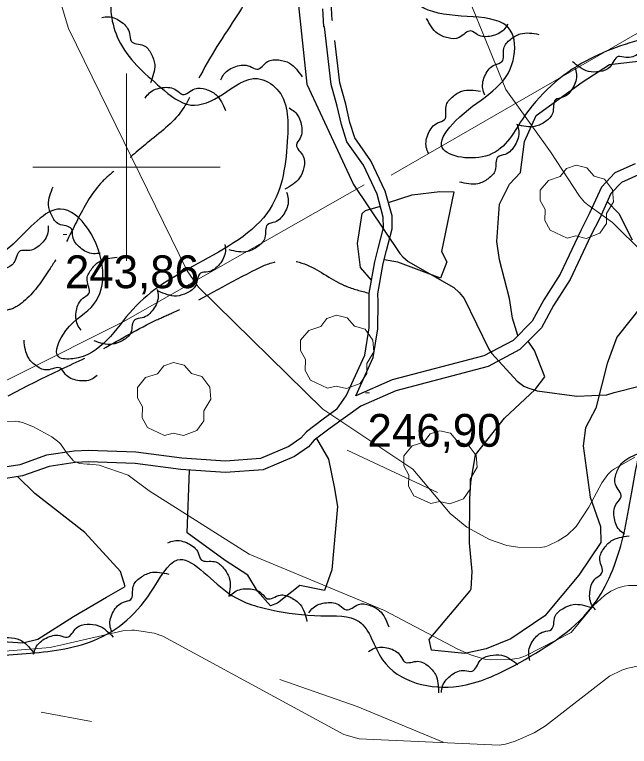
# Model space of a CAD drawing. Extents: x 480269 to 484877, y 4383588 to 4386804.
# Drawn here: x 483470.1 to 483634.3, y 4385345.4 to 4385540.7 of the extents above; entities that cross this region are included whole.
import ezdxf

# ---------------------------------------------------------------- set-up
doc = ezdxf.new("R2010")
doc.units = 0
doc.header["$LTSCALE"] = 3.8
doc.linetypes.add('LONG_DASHED', pattern=[7.5, 6, -1.5])
doc.linetypes.add('MEDIUM_DASHED', pattern=[4.5, 3, -1.5])
for name, color, linetype, lineweight in [('1', 7, 'Continuous', 13), ('25', 7, 'LONG_DASHED', 25), ('27', 7, 'Continuous', 25), ('29', 7, 'Continuous', 13), ('38', 7, 'Continuous', 25), ('51', 7, 'Continuous', 13), ('7', 7, 'Continuous', 13), ('8', 7, 'Continuous', 25), ('9', 7, 'Continuous', 13)]:
    doc.layers.add(name, color=color, linetype=linetype, lineweight=lineweight)

msp = doc.modelspace()

# ---------------------------------------------------------------- linework, layer by layer
at = {"layer": '1'}
for p, q in [((483500, 4385525), (483500, 4385475)), ((483475, 4385500), (483525, 4385500))]:
    msp.add_line(p, q, dxfattribs=at)
at = {"layer": '25'}
for points in [[(483604.54, 4385455.06), (483603.13, 4385459.72), (483602.33, 4385464.95), (483599.66, 4385475.32), (483598.97, 4385480.21), (483599.64, 4385490.14), (483602.36, 4385495.49), (483605.27, 4385498.55), (483606.36, 4385506.84), (483609.46, 4385513.76), (483621.7, 4385522.66), (483629.01, 4385527.38), (483640.73, 4385528.77), (483647.46, 4385528.09), (483656.5, 4385525.57), (483656.93, 4385519.13), (483653.39, 4385515.14), (483647.44, 4385510.87), (483651.9, 4385507.54), (483655.22, 4385504.23)], [(483569.98, 4385490.59), (483576.34, 4385492.58), (483583.7, 4385493.53), (483587.45, 4385493.45), (483584.2, 4385477.46), (483585.56, 4385474.7), (483583.9, 4385470.39), (483572.48, 4385474.63), (483568.86, 4385475.26)], [(483565.46, 4385469.83), (483562.51, 4385473.22), (483561.74, 4385479.61), (483562.97, 4385487.67), (483563.84, 4385488.41), (483567.84, 4385489.6)], [(483628.43, 4385490.8), (483631.55, 4385487.62), (483635.1, 4385480.65)], [(483637.54, 4385462.92), (483630.95, 4385454.65), (483628.38, 4385447.63), (483625.35, 4385435.71), (483622.58, 4385430.41), (483621.96, 4385425.67), (483623.88, 4385411.98), (483626.63, 4385404.12), (483626.74, 4385399.8), (483620.88, 4385391.11), (483611.78, 4385380.29), (483602.69, 4385374.1), (483596.05, 4385371.45), (483590.43, 4385370.22), (483581.47, 4385371.08), (483580.84, 4385373.94), (483591.84, 4385386.97), (483592.05, 4385387.43), (483592.38, 4385392.09), (483591.62, 4385399.76), (483591.76, 4385411.51), (483591.97, 4385415.95), (483593.27, 4385423.22), (483601, 4385432.98), (483609.16, 4385440.64), (483611.73, 4385444.09), (483609, 4385451.06), (483607.32, 4385453.54)], [(483550.76, 4385427.56), (483554, 4385422.06), (483555.52, 4385414.69), (483556.41, 4385409.48), (483554.84, 4385392.51), (483552.91, 4385387.01), (483546.35, 4385388.34), (483540.37, 4385383.68), (483538.47, 4385382.93), (483535.04, 4385386.86), (483532.44, 4385391.15), (483526.35, 4385395.05), (483516.2, 4385402.4), (483516.86, 4385419.18)], [(483409.23, 4385391.99), (483412.22, 4385387.81), (483418.41, 4385380.86), (483426.24, 4385372.32), (483432.23, 4385365.76), (483435.41, 4385363.94), (483440.59, 4385368.76), (483443.75, 4385372.94), (483450.48, 4385375.88), (483462.54, 4385373.64), (483472.32, 4385373.1), (483476.31, 4385374.03), (483485.84, 4385380.07), (483494.71, 4385385.22), (483499.63, 4385388.12), (483498.39, 4385392.12), (483488.93, 4385402.47), (483475.52, 4385412.88), (483470.95, 4385417.41)]]:
    msp.add_lwpolyline(points, dxfattribs=at)
at = {"layer": '27'}
for points in [[(483603.65, 4385366.99), (483624.2, 4385382.47), (483632.03, 4385398.91), (483636.72, 4385422.41), (483645.34, 4385439.65), (483660.21, 4385444.35), (483671.96, 4385455.31), (483662.56, 4385467.06), (483659.43, 4385476.46), (483674.31, 4385492.91), (483694.66, 4385499.96), (483704.06, 4385490.56), (483711.11, 4385468.63), (483722.85, 4385451.4), (483736.16, 4385456.1), (483742.42, 4385467.85), (483748.69, 4385484.3), (483759.65, 4385490.56), (483776.88, 4385484.3), (483802.71, 4385469.41), (483826.99, 4385463.15), (483860.65, 4385463.15), (483873.96, 4385476.46), (483902.15, 4385486.65), (483911.55, 4385506.23), (483932.69, 4385513.28), (483942.86, 4385514.85), (483932.69, 4385531.3), (483915.46, 4385547.75), (483903.72, 4385547.75), (483886.49, 4385539.13), (483871.61, 4385529.73), (483863.78, 4385533.65), (483865.35, 4385544.61), (483871.61, 4385560.28), (483873.96, 4385572.03), (483874.75, 4385588.48), (483884.93, 4385596.31), (483910.76, 4385592.4), (483924.07, 4385597.1), (483936.6, 4385618.25), (483939.73, 4385664.46), (483945.7, 4385679.85)], [(483546.8, 4385573.01), (483530.82, 4385569.72), (483504.5, 4385557.5), (483496.51, 4385547.62), (483497.92, 4385533.98), (483509.2, 4385521.29), (483517.19, 4385516.59), (483525.65, 4385519.41), (483535.05, 4385523.64), (483540.22, 4385520.82), (483543.04, 4385508.12), (483538.34, 4385488.84), (483519.07, 4385474.27), (483501.68, 4385462.04), (483485.7, 4385448.88), (483481.94, 4385449.35), (483483.82, 4385456.4), (483491.34, 4385463.45), (483493.69, 4385472.39), (483482.41, 4385488.84), (483469.72, 4385479.44), (483457.5, 4385473.8), (483447.16, 4385476.15), (483435.41, 4385469.57), (483432.12, 4385452.64), (483431.65, 4385426.31), (483427.89, 4385415.96), (483416.61, 4385410.32), (483407.68, 4385404.21), (483394.53, 4385402.8), (483381.37, 4385399.03), (483373.85, 4385390.57), (483366.33, 4385379.29), (483360.69, 4385372.7), (483348.47, 4385369.41), (483324.97, 4385367.06), (483298.65, 4385356.72), (483277.03, 4385345.43), (483258.23, 4385329.91), (483253.06, 4385332.26), (483259.17, 4385339.32), (483268.1, 4385347.78), (483265.28, 4385357.19), (483251.65, 4385366.59), (483243.66, 4385376.46), (483231.44, 4385369.41), (483229.09, 4385383.05), (483230.97, 4385390.1)], [(483677.76, 4385562.31), (483673.47, 4385559.38), (483664.07, 4385546.21), (483641.98, 4385535.4), (483622.71, 4385528.34), (483605.79, 4385512.83), (483595.92, 4385502.95), (483584.17, 4385505.77), (483587.93, 4385512.36), (483602.97, 4385527.4), (483602.97, 4385535.87), (483581.82, 4385541.51), (483567.25, 4385554.67), (483546.8, 4385573.01)], [(483493.46, 4385539.96), (483495.23, 4385540.15), (483498.73, 4385538.7), (483500.85, 4385535.67), (483501.26, 4385533.66), (483504.61, 4385532.47), (483506.63, 4385530.26), (483507.55, 4385527.38), (483506.43, 4385522.55)], [(483601.83, 4385538.16), (483600.83, 4385536.7), (483597.44, 4385534.99), (483593.77, 4385535.36), (483591.97, 4385536.36), (483588.88, 4385534.6), (483585.9, 4385534.51), (483583.11, 4385535.68), (483580.19, 4385539.69)], [(483595.71, 4385519.26), (483595.17, 4385520.95), (483595.89, 4385524.67), (483598.43, 4385527.35), (483600.31, 4385528.16), (483600.81, 4385531.68), (483602.57, 4385534.1), (483605.2, 4385535.58), (483610.16, 4385535.45)], [(483639.76, 4385534.93), (483639.39, 4385533.2), (483636.9, 4385530.33), (483633.37, 4385529.28), (483631.33, 4385529.52), (483629.13, 4385526.72), (483626.41, 4385525.5), (483623.39, 4385525.54), (483619.16, 4385528.13)], [(483525.22, 4385523.27), (483526.06, 4385524.83), (483529.25, 4385526.89), (483532.94, 4385526.92), (483534.83, 4385526.12), (483537.71, 4385528.2), (483540.67, 4385528.62), (483543.57, 4385527.75), (483546.91, 4385524.08)], [(483619.79, 4385526.56), (483620.22, 4385524.84), (483619.25, 4385521.17), (483616.54, 4385518.66), (483614.6, 4385517.98), (483613.87, 4385514.5), (483611.96, 4385512.21), (483609.23, 4385510.91), (483604.29, 4385511.37)], [(483505.05, 4385518.46), (483506.17, 4385519.83), (483509.68, 4385521.25), (483513.32, 4385520.59), (483515.02, 4385519.44), (483518.25, 4385520.94), (483521.23, 4385520.79), (483523.91, 4385519.38), (483526.49, 4385515.15)], [(483580.69, 4385503.65), (483580.09, 4385505.32), (483580.68, 4385509.06), (483583.12, 4385511.83), (483584.98, 4385512.71), (483585.36, 4385516.24), (483587.02, 4385518.72), (483589.61, 4385520.29), (483594.57, 4385520.33)], [(483543.43, 4385515.8), (483544.92, 4385514.82), (483546.69, 4385511.47), (483546.39, 4385507.79), (483545.42, 4385505.97), (483547.24, 4385502.92), (483547.39, 4385499.93), (483546.26, 4385497.13), (483542.31, 4385494.13)], [(483604.33, 4385511.34), (483604.77, 4385509.62), (483603.83, 4385505.94), (483601.14, 4385503.41), (483599.21, 4385502.71), (483598.51, 4385499.23), (483596.62, 4385496.92), (483593.9, 4385495.59), (483588.96, 4385496.02)], [(483152.78, 4385510.55), (483142.48, 4385493.89), (483124.47, 4385470.39), (483116.64, 4385454.72), (483116.64, 4385442.97), (483122.9, 4385434.36), (483136.21, 4385436.71), (483163.62, 4385469.61), (483173.8, 4385481.36), (483179.28, 4385475.09), (483185.54, 4385443.76), (483202.77, 4385387.36), (483200.42, 4385363.07), (483202.77, 4385344.27), (483193.37, 4385323.91), (483203.55, 4385309.02), (483219.21, 4385299.62), (483231.74, 4385296.49), (483252.09, 4385301.97), (483283.41, 4385323.12), (483318.65, 4385327.04), (483364.06, 4385322.34), (483395.38, 4385316.86), (483400.86, 4385327.82), (483389.11, 4385345.84), (483388.33, 4385359.16), (483402.42, 4385367.77), (483422, 4385368.56), (483431.39, 4385363.86), (483453.32, 4385367.77), (483472.11, 4385370.12), (483490.12, 4385373.26), (483506.56, 4385386.57), (483513.61, 4385395.19), (483526.92, 4385386.57), (483538.66, 4385381.87), (483551.97, 4385380.31), (483562.15, 4385378.74), (483568.41, 4385368.56), (483588.77, 4385361.51), (483603.65, 4385366.99)], [(483492.95, 4385477.04), (483491.18, 4385476.9), (483487.72, 4385478.44), (483485.68, 4385481.52), (483485.32, 4385483.55), (483482, 4385484.83), (483480.05, 4385487.09), (483479.2, 4385489.99), (483480.46, 4385494.79)], [(483542.77, 4385493.3), (483543.22, 4385491.58), (483542.3, 4385487.9), (483539.62, 4385485.36), (483537.69, 4385484.66), (483537, 4385481.17), (483535.12, 4385478.85), (483532.41, 4385477.51), (483527.46, 4385477.92)], [(483479.14, 4385484.34), (483479.05, 4385482.56), (483477.05, 4385479.34), (483473.73, 4385477.74), (483471.67, 4385477.65), (483469.96, 4385474.54), (483467.46, 4385472.9), (483464.47, 4385472.45), (483459.88, 4385474.34)], [(483526.3, 4385479.36), (483526.45, 4385477.59), (483524.9, 4385474.12), (483521.81, 4385472.09), (483519.79, 4385471.73), (483518.5, 4385468.42), (483516.25, 4385466.47), (483513.34, 4385465.62), (483508.55, 4385466.88)], [(483487.93, 4385456.51), (483486.95, 4385457.99), (483486.65, 4385461.77), (483488.37, 4385465.03), (483489.98, 4385466.32), (483489.51, 4385469.85), (483490.55, 4385472.64), (483492.69, 4385474.78), (483497.5, 4385475.98)], [(483508.2, 4385467.34), (483508.47, 4385465.58), (483507.16, 4385462.02), (483504.23, 4385459.78), (483502.23, 4385459.28), (483501.18, 4385455.89), (483499.06, 4385453.78), (483496.22, 4385452.74), (483491.35, 4385453.66)], [(483492.21, 4385444.41), (483490.74, 4385443.42), (483486.96, 4385443.09), (483483.68, 4385444.78), (483482.38, 4385446.37), (483478.86, 4385445.88), (483476.05, 4385446.9), (483473.9, 4385449.02), (483472.66, 4385453.82)], [(483633.02, 4385402.07), (483631.66, 4385403.2), (483630.26, 4385406.73), (483630.97, 4385410.35), (483632.12, 4385412.05), (483630.65, 4385415.29), (483630.83, 4385418.27), (483632.26, 4385420.93), (483636.51, 4385423.48)], [(483511.06, 4385399.75), (483512.74, 4385400.3), (483516.47, 4385399.61), (483519.17, 4385397.1), (483520, 4385395.22), (483523.52, 4385394.74), (483525.95, 4385393.01), (483527.46, 4385390.39), (483527.36, 4385385.43)], [(483625.27, 4385381.83), (483624.25, 4385383.28), (483623.83, 4385387.05), (483625.46, 4385390.37), (483627.02, 4385391.7), (483626.45, 4385395.21), (483627.4, 4385398.04), (483629.48, 4385400.24), (483634.25, 4385401.58)], [(483496.07, 4385375.98), (483495.62, 4385377.7), (483496.53, 4385381.38), (483499.21, 4385383.93), (483501.14, 4385384.63), (483501.82, 4385388.12), (483503.7, 4385390.44), (483506.41, 4385391.79), (483511.35, 4385391.39)], [(483527.61, 4385385.5), (483528.94, 4385386.67), (483532.65, 4385387.5), (483536.12, 4385386.24), (483537.61, 4385384.84), (483541.04, 4385385.78), (483543.96, 4385385.14), (483546.37, 4385383.32), (483548.22, 4385378.72)], [(483548.71, 4385381.06), (483549.86, 4385382.41), (483553.4, 4385383.77), (483557.02, 4385383.04), (483558.71, 4385381.86), (483561.96, 4385383.3), (483564.94, 4385383.09), (483567.59, 4385381.64), (483570.1, 4385377.36)], [(483607.75, 4385368.37), (483607.44, 4385370.12), (483608.65, 4385373.71), (483611.52, 4385376.03), (483613.5, 4385376.58), (483614.47, 4385380), (483616.53, 4385382.16), (483619.34, 4385383.28), (483624.23, 4385382.48)], [(483475.23, 4385370.06), (483475.79, 4385371.75), (483478.57, 4385374.33), (483482.2, 4385374.99), (483484.2, 4385374.53), (483486.68, 4385377.08), (483489.52, 4385378), (483492.52, 4385377.64), (483496.45, 4385374.61)], [(483453.62, 4385367.8), (483454.32, 4385369.43), (483457.32, 4385371.76), (483460.99, 4385372.11), (483462.95, 4385371.48), (483465.64, 4385373.8), (483468.55, 4385374.47), (483471.51, 4385373.85), (483475.15, 4385370.49)], [(483564.69, 4385370.76), (483566.24, 4385371.62), (483570.04, 4385371.63), (483573.16, 4385369.65), (483574.31, 4385367.96), (483577.87, 4385368.14), (483580.57, 4385366.89), (483582.54, 4385364.59), (483583.36, 4385359.7)], [(483584.14, 4385359.81), (483584.46, 4385361.55), (483586.85, 4385364.5), (483590.35, 4385365.67), (483592.39, 4385365.5), (483594.49, 4385368.37), (483597.17, 4385369.68), (483600.2, 4385369.75), (483604.51, 4385367.3)]]:
    msp.add_spline(points, degree=3, dxfattribs=at)
at = {"layer": '29'}
for points in [[(483617.72, 4385481.09), (483613.18, 4385483.21), (483611.77, 4385485.75), (483611.87, 4385488.73), (483610.5, 4385491.14), (483610.54, 4385493.89), (483612.7, 4385496.49), (483615.89, 4385497.49), (483617.54, 4385499.68), (483620.11, 4385500.51), (483622.97, 4385499.86), (483624.92, 4385497.59), (483627.73, 4385496.77), (483629.86, 4385493.92), (483630.1, 4385490.79), (483628.22, 4385487.64), (483628.22, 4385484.96), (483626.4, 4385482.35), (483622.78, 4385481.01), (483620.01, 4385481.64)], [(483553.72, 4385441.05), (483549.18, 4385443.17), (483547.77, 4385445.71), (483547.87, 4385448.69), (483546.5, 4385451.1), (483546.54, 4385453.85), (483548.7, 4385456.45), (483551.89, 4385457.45), (483553.54, 4385459.64), (483556.11, 4385460.47), (483558.97, 4385459.82), (483560.92, 4385457.55), (483563.73, 4385456.73), (483565.86, 4385453.88), (483566.1, 4385450.75), (483564.22, 4385447.6), (483564.22, 4385444.92), (483562.4, 4385442.31), (483558.78, 4385440.97), (483556.01, 4385441.6)], [(483510.16, 4385428.43), (483505.62, 4385430.55), (483504.21, 4385433.09), (483504.31, 4385436.07), (483502.94, 4385438.48), (483502.98, 4385441.23), (483505.14, 4385443.83), (483508.33, 4385444.83), (483509.98, 4385447.02), (483512.55, 4385447.85), (483515.41, 4385447.2), (483517.36, 4385444.93), (483520.17, 4385444.11), (483522.3, 4385441.26), (483522.54, 4385438.13), (483520.66, 4385434.98), (483520.66, 4385432.3), (483518.84, 4385429.69), (483515.22, 4385428.35), (483512.45, 4385428.98)], [(483581.31, 4385410.21), (483576.77, 4385412.33), (483575.36, 4385414.87), (483575.46, 4385417.85), (483574.09, 4385420.26), (483574.13, 4385423.01), (483576.29, 4385425.61), (483579.48, 4385426.61), (483581.13, 4385428.8), (483583.7, 4385429.63), (483586.56, 4385428.98), (483588.51, 4385426.71), (483591.32, 4385425.89), (483593.45, 4385423.04), (483593.69, 4385419.91), (483591.81, 4385416.76), (483591.81, 4385414.08), (483589.99, 4385411.47), (483586.37, 4385410.13), (483583.6, 4385410.76)]]:
    msp.add_lwpolyline(points, close=True, dxfattribs=at)
at = {"layer": '38', "linetype": 'MEDIUM_DASHED'}
msp.add_lwpolyline([(483561.28, 4385439.02), (483565.89, 4385449.17), (483567.14, 4385456.9), (483567.2, 4385464.1), (483567.16, 4385466.2), (483568.62, 4385474.3), (483569.47, 4385477.73), (483570.95, 4385483.54), (483570.94, 4385486.99), (483569.15, 4385493.62), (483565.29, 4385501.69), (483560.98, 4385507.84), (483559.66, 4385511.97), (483558.57, 4385516.81), (483557, 4385522.51), (483555.08, 4385539.19), (483554.99, 4385539.22), (483554.78, 4385542.44), (483554.04, 4385551.25), (483553.79, 4385553.9), (483552.16, 4385563.48), (483550.49, 4385569.01), (483550.22, 4385569.85), (483549.87, 4385576.35)], dxfattribs=at)
at = {"layer": '38'}
for points in [[(483556.23, 4385435.44), (483558.73, 4385438.98), (483563.65, 4385449.84), (483564.82, 4385457.09), (483564.88, 4385464.09), (483564.84, 4385466.39), (483566.35, 4385474.78), (483567.22, 4385478.29), (483568.63, 4385483.82), (483568.62, 4385486.68), (483566.96, 4385492.81), (483563.29, 4385500.52), (483558.87, 4385506.8), (483557.42, 4385511.37), (483556.32, 4385516.25), (483554.71, 4385522.07), (483552.94, 4385537.49), (483552.77, 4385537.55), (483552.47, 4385542.27)], [(483635.86, 4385500.86), (483630.44, 4385498.45), (483626.86, 4385494.68), (483623.67, 4385487.74), (483621.34, 4385483.09), (483615.86, 4385471.47), (483611.48, 4385464.63), (483608.41, 4385458.93), (483603.26, 4385453.78), (483595.49, 4385449.63), (483570.98, 4385443.23), (483561.28, 4385439.02)], [(483636.74, 4385497.93), (483632.23, 4385495.92), (483629.41, 4385492.95), (483626.41, 4385486.42), (483624.07, 4385481.76), (483618.52, 4385470), (483614.1, 4385463.09), (483610.87, 4385457.1), (483605.09, 4385451.31), (483596.6, 4385446.78), (483571.98, 4385440.35), (483562.58, 4385436.26), (483554.38, 4385430.36), (483550.19, 4385427.11), (483548.62, 4385425.35), (483544.89, 4385422.77), (483536.57, 4385419.22), (483526.47, 4385418.53), (483514.53, 4385419.34), (483502.3, 4385420.9), (483489.91, 4385421.33), (483486.34, 4385421.2), (483479.37, 4385420.15), (483472.26, 4385417.61), (483467.79, 4385416.91)], [(483556.23, 4385435.44), (483552.56, 4385432.79), (483548.11, 4385429.34), (483546.59, 4385427.64), (483543.41, 4385425.44), (483535.85, 4385422.22), (483526.47, 4385421.57), (483514.83, 4385422.36), (483502.55, 4385423.93), (483489.91, 4385424.37), (483486.06, 4385424.23), (483478.63, 4385423.11), (483471.51, 4385420.57), (483467.56, 4385419.95)]]:
    msp.add_lwpolyline(points, dxfattribs=at)
at = {"layer": '38', "linetype": 'LONG_DASHED'}
for points in [[(483222.84, 4385328.78), (483233.49, 4385331.65), (483248.44, 4385336.61), (483252.54, 4385340.94), (483258.88, 4385354.18), (483261.76, 4385364.09), (483264.07, 4385370.4), (483271.55, 4385381.16), (483280.42, 4385394.23), (483287.47, 4385408.23), (483295.91, 4385425.29), (483304.52, 4385439.96), (483308.91, 4385446.59), (483318.63, 4385460.51), (483325.16, 4385473.38), (483329.03, 4385484.99), (483336.9, 4385500.43), (483342.08, 4385509.3), (483351.29, 4385526.25), (483356.88, 4385535.07), (483367.82, 4385552.46), (483372.61, 4385560.56), (483384.55, 4385574.31), (483394.22, 4385589.19), (483401.11, 4385600.15), (483408.96, 4385613.82), (483416.11, 4385628.46), (483421.62, 4385644.25), (483425.26, 4385652.82), (483437.44, 4385668.5), (483447.61, 4385682.66), (483455.49, 4385695.61), (483457.94, 4385709.1), (483457.8, 4385712.22), (483460.32, 4385716.64), (483471.95, 4385728.32), (483483.41, 4385737.85), (483491.91, 4385744.84), (483502.88, 4385754.26), (483511.53, 4385762), (483517.86, 4385770.14), (483520.82, 4385773.68), (483521.2, 4385789.84), (483522.3, 4385808.2), (483521.83, 4385825.17), (483522.61, 4385837.11), (483524.33, 4385844.04), (483529.61, 4385862.88), (483530.12, 4385879.57), (483529.5, 4385895.4), (483531.44, 4385911.89), (483533.11, 4385922.24), (483534.94, 4385934.41), (483535.75, 4385947.11), (483535.49, 4385954.95), (483538.08, 4385971.48), (483542.8, 4385983), (483551.34, 4385997.49), (483555.36, 4386004.16), (483555.47, 4386004.25)], [(483549.18, 4385565.2), (483543.95, 4385560.32), (483538.38, 4385553.83), (483529.64, 4385540.66), (483519.21, 4385523.41), (483514.75, 4385515.06), (483505.58, 4385506.46), (483497.79, 4385499.89), (483493.59, 4385496.17), (483487.25, 4385486.55), (483482.3, 4385477.14), (483479.01, 4385472.04), (483472.56, 4385464.14), (483468.73, 4385461.99), (483458.51, 4385464.43), (483444.6, 4385463.08), (483435.34, 4385459.51), (483429.43, 4385458.44), (483416.58, 4385458.99), (483403.28, 4385460.76), (483384.88, 4385459.21), (483372.63, 4385454.93), (483365.84, 4385453.56), (483350.1, 4385452.09), (483330.85, 4385457.31), (483319.64, 4385462.11)], [(483448.32, 4385419.72), (483455.27, 4385430.15), (483467.44, 4385438.46), (483480.95, 4385445.3), (483493.72, 4385451.49), (483508.08, 4385459.24), (483512.5, 4385461.23), (483533.63, 4385472.27), (483539.58, 4385474.69), (483545.47, 4385474.8), (483555.97, 4385469.57), (483558.51, 4385468.33), (483564.84, 4385466.39)], [(483795.58, 4385215.69), (483787.52, 4385217.14), (483774.93, 4385219.27), (483756.17, 4385220.84), (483744.1, 4385220.75), (483730.15, 4385220.39), (483717.93, 4385220.89), (483709.9, 4385222.06), (483700.53, 4385223.65), (483694.72, 4385225.88), (483683.27, 4385233.26), (483677.29, 4385236.66), (483662.64, 4385243.79), (483651.72, 4385247.83), (483644.93, 4385250.29), (483635.65, 4385253.31), (483617.57, 4385261.54), (483615.06, 4385263.27), (483612.3, 4385264.61), (483604.76, 4385269), (483594.29, 4385275.78), (483584.82, 4385280.7), (483566.04, 4385290.4), (483555.24, 4385295.34), (483546.21, 4385301.34), (483538.99, 4385305.85), (483528.92, 4385311.04), (483523.21, 4385313.51), (483510.9, 4385315.71), (483494.14, 4385318.51), (483477.95, 4385321.32), (483473.72, 4385322.41), (483455.31, 4385325.65), (483446.94, 4385324.54), (483441.74, 4385325.11), (483434.23, 4385329.08), (483424.38, 4385339.16), (483421.39, 4385345.15), (483417.87, 4385349.13), (483413.47, 4385355.82), (483410.01, 4385363.32), (483406.1, 4385367.21), (483401.43, 4385368.01), (483387.69, 4385374.61)]]:
    msp.add_spline(points, degree=3, dxfattribs=at)
at = {"layer": '51'}
for p, q in [((483570.67, 4385497.84), (483639.54, 4385537.55)), ((483583.09, 4385413.19), (483558.97, 4385424.44)), ((483490.67, 4385352.03), (483477.2, 4385354.57))]:
    msp.add_line(p, q, dxfattribs=at)
for points in [[(483563.54, 4385495.27), (483499.12, 4385458.71), (483444.19, 4385431.26), (483381.87, 4385397.66), (483307.68, 4385358.43), (483243.32, 4385321.98), (483241.23, 4385329.71)], [(483584.63, 4385346.55), (483561.65, 4385356.06), (483541, 4385363.25)]]:
    msp.add_lwpolyline(points, dxfattribs=at)
at = {"layer": '7'}
for p, q in [((483483.09, 4385482.08), (483484.09, 4385482.08)), ((483563.9, 4385439.76), (483564.9, 4385439.76))]:
    msp.add_line(p, q, dxfattribs=at)
at = {"layer": '8'}
for points in [[(483753.34, 4386095.07), (483741.77, 4386077.52), (483729.02, 4386044.1), (483719.89, 4385998.13), (483700.85, 4385936.57), (483673.49, 4385898.65), (483634.96, 4385827.01), (483619.32, 4385779.29), (483617.06, 4385750.43), (483607.42, 4385703.77), (483588.4, 4385668.48), (483553.23, 4385618.74), (483549.49, 4385606.42), (483542.9, 4385571.76), (483548.23, 4385522.15)], [(483548.23, 4385522.15), (483560.67, 4385495.42), (483573.04, 4385476.99), (483573.83, 4385476.1), (483575.24, 4385474.85), (483587.46, 4385467.85), (483588.9, 4385466.55), (483590.17, 4385464.98), (483596.81, 4385451.41), (483597.61, 4385450.32), (483604.37, 4385442.85), (483606.18, 4385441.6), (483607.18, 4385441.11), (483609.67, 4385440.28), (483620.32, 4385438.89), (483628.31, 4385439.23), (483630.26, 4385439.85), (483637.28, 4385441.62)]]:
    msp.add_lwpolyline(points, dxfattribs=at)
at = {"layer": '9'}
for points in [[(483646.34, 4385468.94), (483629.82, 4385485.21), (483623.22, 4385489.98), (483622.38, 4385490.7), (483621.03, 4385492.24), (483613.24, 4385504.08), (483601.37, 4385520.76), (483586.25, 4385557.67), (483587.76, 4385590.43), (483588.94, 4385596.69), (483593.08, 4385607.94), (483595.34, 4385611.54), (483598.94, 4385616.42), (483620.79, 4385663.69), (483626.74, 4385680.5), (483634.36, 4385694.19)], [(483635.77, 4385422.59), (483630.38, 4385419.54), (483629.56, 4385418.95), (483628.59, 4385417.99), (483626.97, 4385415.76), (483623.5, 4385409.25), (483620.08, 4385404.13), (483617.75, 4385401.82), (483615.36, 4385400.26), (483612.77, 4385399.03), (483611.85, 4385398.72), (483611.68, 4385398.68), (483611.67, 4385398.7), (483611.66, 4385398.69), (483611.63, 4385398.67), (483610.56, 4385398.47), (483604.57, 4385398.57), (483601.65, 4385399.08), (483597.02, 4385400.67), (483590.91, 4385403.92), (483586.47, 4385407.57), (483576.52, 4385419.4), (483552.5, 4385435.42), (483519.22, 4385468), (483516.27, 4385472.31), (483484.54, 4385536.97), (483482.02, 4385545.37)], [(483460.01, 4385431.98), (483470.31, 4385432.22), (483471.12, 4385432.1), (483471.27, 4385432.05), (483471.28, 4385432.03), (483471.3, 4385432.02), (483471.34, 4385432.04), (483471.52, 4385432.02), (483472.27, 4385431.83), (483475.15, 4385430.71), (483480.09, 4385428.04), (483482, 4385426.55), (483482.4, 4385426.13), (483484.21, 4385423.6), (483485.81, 4385421.68), (483485.82, 4385421.66), (483487.43, 4385420.88), (483487.44, 4385420.88), (483489.55, 4385420.72), (483489.69, 4385420.74), (483490.23, 4385420.74), (483492.73, 4385420.46), (483500.47, 4385417.81), (483506.06, 4385413.64), (483532.81, 4385396.7), (483568.89, 4385381.69), (483588.53, 4385371.33), (483592.17, 4385369.79), (483596.01, 4385368.63), (483597.16, 4385368.53), (483602.45, 4385368.57), (483604.92, 4385369), (483606.59, 4385369.63), (483618.78, 4385375.85), (483624.77, 4385383.01), (483627.72, 4385385.69), (483629.38, 4385386.83), (483631.3, 4385387.71), (483632.9, 4385388.16), (483634.07, 4385388.32), (483639.18, 4385388.35)], [(483643.03, 4385368.21), (483633.89, 4385366.3), (483632.33, 4385365.81), (483629.02, 4385364.15), (483611.97, 4385350.95), (483608.94, 4385349.04), (483603.87, 4385346.78), (483601.26, 4385346.03), (483599.53, 4385345.73), (483562.18, 4385347.45), (483558.04, 4385348.6), (483509.76, 4385374.88), (483507.39, 4385375.65), (483502.16, 4385376.41), (483501.43, 4385376.44), (483499.03, 4385376.22), (483479.64, 4385371.79), (483466.45, 4385370.78)]]:
    msp.add_lwpolyline(points, dxfattribs=at)

# ---------------------------------------------------------------- texts
at = {"layer": '7'}
for s, p in [('243,86', (483483.59, 4385467.71)), ('246,90', (483564.4, 4385425.39))]:
    msp.add_text(s, height=8.75, dxfattribs=at).set_placement(p)

doc.saveas('drawing.dxf')
